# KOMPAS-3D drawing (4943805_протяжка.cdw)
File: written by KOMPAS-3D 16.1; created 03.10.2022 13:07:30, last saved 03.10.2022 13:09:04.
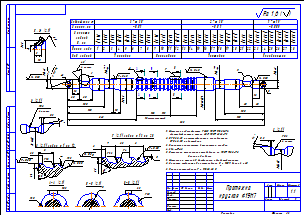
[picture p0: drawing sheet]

Sheet 1: A3, landscape

Title block, sheet 1: name: Протяжка / круглая  19Н7; scale: 1:1; sheets: 1; sheet format: A3

Views: Вид зубьев
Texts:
  Ra 0,80
  Ra 0,40
  Ra 0,20
  1. Материал рабочей части Р6М5 ГОСТ 19265-73;
  хвостовой части - сталь 40Х ГОСТ 4543-71
  2. НRC 62...65 - режущей части и направляющих,
  HRC 42...50 - хвостовика
  3. Выкружки расположить в шахматном порядке.
  4. h14,  IT/2
  5. Остальные технические требования по ГОСТ 9126-76
  1. Материал - сталь 45 2-ой группы обрабатываемости
  2. Диаметр отверстия до протягивания D o = 18Н9, длина L = 40
  3. Усилие протягивания P = 19226,22 Н
  Г (2:1) зубья с 13 по 28
  Д (2:1) зубья с 1 по 12
  Задний угол
  Допуск, мм
  Диаметр
  зубьев
  D, мм
  Номер зуба
  Черновые
  Чистовые
  Калибрующие
  Переходные
  Ra 1,6
  Ra 1,6 ( )
Dimensions and other numbers on the sheet: 20; 100; 150; 10; 245; 102; 115; 16 переменных шагов; 12; 16; 2 места; 4 места; 17; 565; 14; 19,021; 4; 8,5; 5; 7; 6,5; 6; 2; 2,5; 10,5; 3,5; 8; 3,6; 0,5; 9,5; 11; -0,01; 1; 13; -0,005; 23; 3; 9; 15; 18; 19; 21; 22; 24; 25; 26; 27; 28; 17,75; 18,81; 17,95; 17,93; 18,15; 18,13; 18,35; 18,55; 18,63; 18,75; 18,86; 18,91; 18,96; 18,98; 19,00; 19,01; 19,02; 1:1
